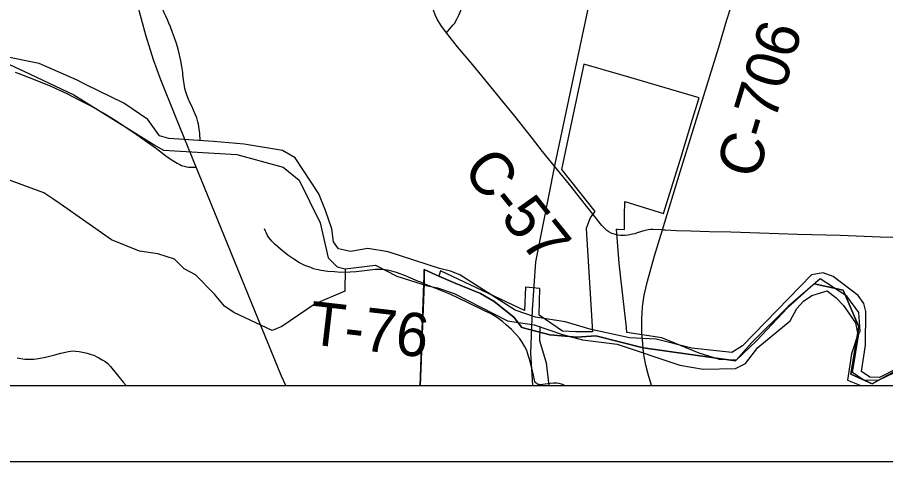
# Model space of a CAD drawing. Extents: x 0 to 34, y 0 to 22.
# Drawn here: x 5.439 to 6.577, y 14 to 14.583 of the extents above; entities that cross this region are included whole.
import ezdxf

# ---------------------------------------------------------------- set-up
doc = ezdxf.new("R2010")
doc.units = 0
for name, color, linetype in [('GM_X_Corporation', 7, 'Continuous'), ('GM_X_County_Road', 7, 'Continuous'), ('GM_X_County_Road_Text', 7, 'Continuous'), ('GM_X_Minor_River', 7, 'Continuous'), ('GM_X_Rail_Line', 7, 'Continuous'), ('GM_X_State_Route', 7, 'Continuous'), ('GM_X_Township_Road', 7, 'Continuous'), ('GM_X_Township_Road_Text', 7, 'Continuous'), ('SH_Data', 7, 'Continuous')]:
    doc.layers.add(name, color=color, linetype=linetype)

msp = doc.modelspace()

# ---------------------------------------------------------------- linework, layer by layer
at = {"layer": 'GM_X_Corporation'}
for points in [[(2.1, 16.4477), (2.1, 14.1), (8.9, 14.1), (8.9, 16.2485)], [(6.5874, 14.1159), (6.568, 14.1068), (6.5489, 14.1063), (6.5333, 14.1171), (6.5417, 14.1676), (6.5435, 14.1713), (6.5416, 14.1955), (6.5261, 14.2168), (6.4913, 14.2397), (6.4492, 14.2036), (6.4012, 14.1556), (6.381, 14.133), (6.3591, 14.134), (6.3327, 14.1422), (6.2836, 14.1624), (6.2378, 14.1695), (6.2371, 14.1759), (6.2298, 14.2407), (6.2275, 14.2601), (6.2242, 14.3049), (6.2259, 14.3048), (6.2346, 14.3046), (6.2348, 14.3229), (6.2349, 14.3412), (6.2732, 14.3293), (6.2859, 14.3254), (6.3092, 14.4009), (6.3235, 14.4476), (6.3325, 14.4771), (6.2507, 14.501), (6.2506, 14.5011), (6.2299, 14.5071), (6.1811, 14.5214), (6.1625, 14.4327), (6.1521, 14.3829), (6.1955, 14.3282), (6.1901, 14.3204), (6.1884, 14.316), (6.1844, 14.3059), (6.1926, 14.1704), (6.1706, 14.1701), (6.1534, 14.1712), (6.1227, 14.1919), (6.1234, 14.2269), (6.1047, 14.2289), (6.1037, 14.198), (5.9932, 14.25), (5.9912, 14.2433), (5.9719, 14.2518), (5.971, 14.2336), (5.9661, 14.1), (6.701, 14.1)], [(2.1, 14.1), (5.9669, 14.1), (5.9718, 14.2339), (5.9719, 14.2518), (5.9912, 14.2433), (6.0106, 14.2347), (6.0457, 14.2204), (6.0638, 14.2101), (6.0897, 14.1893), (6.1001, 14.176), (6.1365, 14.1664), (6.1722, 14.163), (6.1971, 14.165), (6.2589, 14.1491), (6.3803, 14.132), (6.4075, 14.1583), (6.4485, 14.2016), (6.4833, 14.2331), (6.5212, 14.2247), (6.5417, 14.1767), (6.5313, 14.1149), (6.5592, 14.1021), (6.5997, 14.1245)], [(6.5997, 14.1245), (6.5592, 14.1021), (6.5313, 14.1149), (6.5417, 14.1767), (6.5212, 14.2247), (6.4833, 14.2331), (6.4485, 14.2016), (6.4075, 14.1583), (6.3803, 14.132), (6.2589, 14.1491), (6.1971, 14.165), (6.1722, 14.163), (6.1365, 14.1664), (6.1001, 14.176), (6.0897, 14.1893), (6.0638, 14.2101), (6.0457, 14.2204), (6.0106, 14.2347), (5.9912, 14.2433), (5.9719, 14.2518), (5.9718, 14.2339), (5.9669, 14.1), (6.697, 14.1)]]:
    msp.add_lwpolyline(points, dxfattribs=at)
at = {"layer": 'GM_X_County_Road'}
for points in [[(6.0011, 14.5624), (5.9938, 14.5722), (5.9891, 14.5803), (5.9864, 14.586), (5.9843, 14.592), (5.9829, 14.5981), (5.9822, 14.6044), (5.982, 14.6107), (5.9823, 14.6169), (5.9833, 14.6263), (5.985, 14.6355), (5.9886, 14.6506), (5.995, 14.6747), (6.0056, 14.7136), (6.0116, 14.7377), (6.0205, 14.777), (6.0255, 14.8013), (6.0321, 14.8348), (6.037, 14.8592), (6.0386, 14.8683), (6.0392, 14.8775), (6.0392, 14.8806)], [(6.2845, 14.3041), (6.3077, 14.3799), (6.3425, 14.493), (6.3582, 14.5435), (6.3689, 14.5793), (6.3801, 14.6149), (6.4001, 14.6803), (6.4089, 14.7086), (6.414, 14.7253)], [(6.1935, 14.324), (6.1835, 14.3366), (6.1623, 14.3634), (6.1426, 14.3874), (6.1272, 14.4068), (6.1138, 14.4238), (6.0907, 14.453), (6.0514, 14.5011), (6.0357, 14.5203), (6.0157, 14.5441), (6.0011, 14.5624)], [(5.4356, 14.5106), (5.4406, 14.5089), (5.4597, 14.5017), (5.4823, 14.4923), (5.5033, 14.4826), (5.5191, 14.4746), (5.534, 14.4669), (5.5433, 14.4618), (5.5542, 14.4555), (5.5704, 14.4456), (5.5945, 14.4293), (5.6209, 14.4104), (5.6352, 14.3999), (5.6436, 14.3941), (5.6479, 14.3915), (5.6515, 14.3895), (5.654, 14.3883), (5.6571, 14.3873), (5.6602, 14.3867), (5.6631, 14.3863), (5.6731, 14.386)], [(6.2251, 14.2973), (6.223, 14.2978), (6.2199, 14.2987), (6.217, 14.2998), (6.2142, 14.3014), (6.2115, 14.3032), (6.2091, 14.3052), (6.2048, 14.3098), (6.1935, 14.324)], [(6.2845, 14.3041), (6.2718, 14.3045), (6.2688, 14.3044), (6.2658, 14.304), (6.2599, 14.3026), (6.251, 14.2999), (6.248, 14.2989), (6.245, 14.2981), (6.2388, 14.297), (6.2356, 14.2966), (6.2324, 14.2965), (6.2293, 14.2967), (6.2261, 14.2971), (6.2251, 14.2973)], [(6.2596, 14.1435), (6.2591, 14.1485), (6.2581, 14.16), (6.2572, 14.1687), (6.2572, 14.1874), (6.2582, 14.203), (6.2604, 14.2185), (6.2646, 14.2368), (6.274, 14.2698), (6.2845, 14.3041)], [(6.2845, 14.3041), (6.2878, 14.3039), (6.3028, 14.3032), (6.3214, 14.3025), (6.3462, 14.3016), (6.3742, 14.3012), (6.4115, 14.3), (6.4612, 14.2981), (6.5172, 14.2969), (6.57, 14.295), (6.6539, 14.2926)], [(6.27, 14.1), (6.269, 14.1028), (6.2655, 14.1146), (6.2625, 14.1265), (6.2607, 14.1356), (6.2599, 14.1405), (6.2596, 14.1435)]]:
    msp.add_lwpolyline(points, dxfattribs=at)
at = {"layer": 'GM_X_Minor_River'}
for points in [[(6.6152, 14.1338), (6.5691, 14.1105), (6.5562, 14.1108), (6.5452, 14.1184), (6.5504, 14.1526), (6.5509, 14.1969), (6.5482, 14.2072), (6.541, 14.2178), (6.508, 14.2427), (6.4951, 14.2476), (6.4799, 14.2449), (6.3891, 14.152), (6.3755, 14.1429), (6.3229, 14.1487), (6.2763, 14.1607), (6.2411, 14.1625), (6.191, 14.1733), (6.1569, 14.1833), (6.118, 14.1896), (6.0914, 14.1988), (6.0189, 14.2448), (6.0064, 14.2497), (5.992, 14.2531), (5.9249, 14.2752), (5.8983, 14.2793), (5.8753, 14.2755), (5.8597, 14.2792), (5.8531, 14.2884), (5.851, 14.3052), (5.8426, 14.3294), (5.8337, 14.3512), (5.8028, 14.3985), (5.7861, 14.4079), (5.7361, 14.4165), (5.6956, 14.4198), (5.6373, 14.4237), (5.6251, 14.4271), (5.6095, 14.4487), (5.5784, 14.4702), (5.5287, 14.4943), (5.5169, 14.5004), (5.4673, 14.5222), (5.4218, 14.5311)], [(5.4226, 14.5232), (5.4472, 14.5119), (5.5125, 14.481), (5.6203, 14.4142), (5.6301, 14.4085), (5.7263, 14.4028), (5.7873, 14.3863), (5.8079, 14.3693), (5.8357, 14.3133), (5.8461, 14.2674), (5.8579, 14.2553), (5.8685, 14.2527), (5.9083, 14.2577), (5.936, 14.2434), (5.9765, 14.2307), (5.9894, 14.2277), (6.0114, 14.2205), (6.0812, 14.1847), (6.1161, 14.1792), (6.1532, 14.1668), (6.1794, 14.1596), (6.2248, 14.1541), (6.3071, 14.1267), (6.3378, 14.1211), (6.3802, 14.122), (6.3934, 14.1285), (6.4096, 14.1498), (6.4518, 14.1848), (6.4605, 14.2008), (6.4691, 14.2103), (6.4804, 14.218), (6.5005, 14.2241), (6.5123, 14.215), (6.5218, 14.2048), (6.5374, 14.1821), (6.5405, 14.1666), (6.5323, 14.1415), (6.5271, 14.1069), (6.5443, 14.1)], [(5.8685, 14.2527), (5.868, 14.2236), (5.829, 14.2071), (5.7855, 14.177), (5.7727, 14.172), (5.7225, 14.1957), (5.71, 14.2039), (5.697, 14.2198), (5.6723, 14.2451), (5.6575, 14.253), (5.6445, 14.2655), (5.6229, 14.2726), (5.5986, 14.2759), (5.5621, 14.2909), (5.4948, 14.3381), (5.4849, 14.3445), (5.4735, 14.3524), (5.4063, 14.3771), (5.3953, 14.3786), (5.3779, 14.3721)], [(6.1237, 14.1766), (6.123, 14.1587), (6.1318, 14.1295), (6.1353, 14.1)]]:
    msp.add_lwpolyline(points, dxfattribs=at)
msp.add_spline([(5.6783, 14.4209), (5.6754, 14.4455), (5.659, 14.4864), (5.6554, 14.5103), (5.6393, 14.5702), (5.6236, 14.6069), (5.6144, 14.6437), (5.5991, 14.6824), (5.5748, 14.6842), (5.5627, 14.6803), (5.5472, 14.6814), (5.537, 14.6878), (5.5039, 14.7234), (5.503, 14.737), (5.5034, 14.7518), (5.5108, 14.7826), (5.5096, 14.8019), (5.5173, 14.8585), (5.5353, 14.8885), (5.5764, 14.9217), (5.5881, 14.9323), (5.6085, 14.9567), (5.6099, 14.9817), (5.6832, 15.0036), (5.6759, 15.0453), (5.6722, 15.1143), (5.6743, 15.2396), (5.6809, 15.2885), (5.6899, 15.3106), (5.6985, 15.3235), (5.7094, 15.333), (5.7276, 15.3331), (5.7382, 15.3376), (5.7483, 15.3616), (5.7616, 15.3643), (5.7869, 15.3625), (5.7895, 15.3769), (5.7967, 15.3891), (5.8269, 15.3888), (5.8833, 15.3985), (5.8977, 15.3981), (5.9257, 15.4096), (5.96, 15.4325), (5.9879, 15.4542), (6.0116, 15.4865), (6.0256, 15.4881), (6.0335, 15.4988), (6.0273, 15.5306), (6.0114, 15.5378), (5.9679, 15.53), (5.9547, 15.5311), (5.8376, 15.5489), (5.8028, 15.5507), (5.7774, 15.5567), (5.7679, 15.5586), (5.7406, 15.5763), (5.7557, 15.5862), (5.7807, 15.5851), (5.7991, 15.6076), (5.8142, 15.6141), (5.8248, 15.6229), (5.8526, 15.6651), (5.8764, 15.6883), (5.8923, 15.6933), (5.9343, 15.6991), (6.0268, 15.748), (6.0921, 15.7979), (6.1098, 15.8059), (6.1204, 15.8075)], degree=3, dxfattribs=at)
at = {"layer": 'GM_X_Rail_Line'}
msp.add_lwpolyline([(6.1146, 14.1), (6.1117, 14.1427), (6.1139, 14.1992), (6.1185, 14.2621), (6.1439, 14.39), (6.2167, 14.7339), (6.2496, 14.888), (6.2719, 14.9805), (6.2786, 15.0391), (6.2721, 15.0825), (6.2575, 15.1281)], dxfattribs=at)
at = {"layer": 'GM_X_State_Route'}
msp.add_lwpolyline([(5.7904, 14.1), (5.7849, 14.1121), (5.684, 14.3594), (5.6731, 14.386), (5.6464, 14.4515), (5.6267, 14.5005), (5.6173, 14.5268), (5.6072, 14.5594), (5.5956, 14.6013)], dxfattribs=at)
at = {"layer": 'GM_X_Township_Road'}
for points in [[(6.0011, 14.5624), (6.0097, 14.5722), (6.0115, 14.5747), (6.0147, 14.58), (6.0175, 14.5856), (6.0198, 14.5914), (6.0213, 14.5973), (6.023, 14.6096), (6.0262, 14.6311), (6.0273, 14.6372), (6.0289, 14.6432), (6.0311, 14.649), (6.0368, 14.66), (6.0512, 14.6875), (6.054, 14.693)], [(5.9674, 14.2352), (5.9646, 14.2364), (5.9473, 14.2435), (5.9357, 14.248), (5.9297, 14.2498), (5.9236, 14.251), (5.9176, 14.2518), (5.9112, 14.2519), (5.9081, 14.2518), (5.8826, 14.2487), (5.8748, 14.2483), (5.8628, 14.2481), (5.8544, 14.2487), (5.8457, 14.2493), (5.8368, 14.2506), (5.8307, 14.2519), (5.8268, 14.253), (5.8232, 14.2544), (5.8157, 14.2574), (5.8086, 14.2609), (5.801, 14.2654), (5.7934, 14.2708), (5.7836, 14.2786), (5.7766, 14.2848), (5.7722, 14.2892), (5.7683, 14.2941), (5.7666, 14.2967), (5.7651, 14.2994), (5.7638, 14.3022), (5.7626, 14.3051)], [(6.1559, 14.1), (6.1555, 14.1002), (6.1522, 14.1016), (6.1489, 14.1025), (6.1458, 14.1029), (6.1415, 14.1029), (6.1371, 14.1026), (6.1274, 14.1011), (6.1243, 14.1009), (6.1225, 14.101), (6.1211, 14.1013), (6.1199, 14.1019), (6.1188, 14.1029), (6.1177, 14.1039), (6.117, 14.1053), (6.1164, 14.1069), (6.1152, 14.1137), (6.1099, 14.1342), (6.1084, 14.1398), (6.1064, 14.1456), (6.1036, 14.1514), (6.1003, 14.1567), (6.0968, 14.1617), (6.0921, 14.167), (6.0863, 14.1731), (6.0795, 14.1795), (6.0748, 14.1836), (6.0666, 14.1896), (6.0587, 14.1942), (6.0517, 14.1974), (6.0277, 14.2093), (6.0068, 14.219), (5.9937, 14.2244), (5.972, 14.2333), (5.9674, 14.2352)], [(5.4385, 14.136), (5.4483, 14.1345), (5.4539, 14.1342), (5.4602, 14.1343), (5.4664, 14.1351), (5.4755, 14.1371), (5.4876, 14.1401), (5.4957, 14.1423), (5.5056, 14.1444), (5.5086, 14.1448), (5.5116, 14.1452), (5.515, 14.145), (5.5195, 14.1446), (5.5242, 14.1437), (5.5301, 14.1424), (5.5355, 14.1407), (5.5388, 14.1394), (5.5421, 14.1379), (5.5455, 14.1362), (5.5507, 14.1331), (5.5539, 14.1311), (5.5571, 14.1286), (5.5607, 14.1246), (5.5682, 14.1154), (5.5774, 14.1042), (5.581, 14.1002), (5.5812, 14.1)]]:
    msp.add_lwpolyline(points, dxfattribs=at)
at = {"layer": 'SH_Data'}
for p, q in [((2.1, 14.1), (8.9, 14.1)), ((2, 14), (9, 14))]:
    msp.add_line(p, q, dxfattribs=at)

# ---------------------------------------------------------------- texts
at = {"layer": 'GM_X_County_Road_Text'}
for s, rotation, p in [('C-706', 73.1209, (6.4082, 14.3685)), ('C-57', 308.7654, (6.0206, 14.3822))]:
    msp.add_text(s, height=0.05682, rotation=rotation, dxfattribs=at).set_placement(p)
at = {"layer": 'GM_X_Township_Road_Text'}
msp.add_text('T-76', height=0.05682, rotation=353.385, dxfattribs=at).set_placement((5.8191, 14.1543))

doc.saveas('drawing.dxf')
